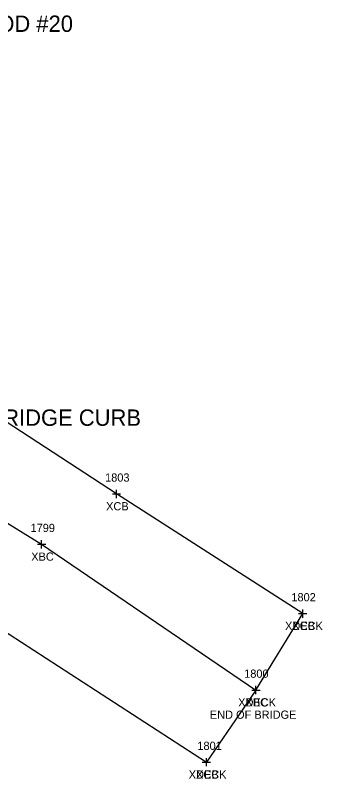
# Model space of a CAD drawing. Extents: x 1657482 to 1661439, y 647981 to 649041.
# Drawn here: x 1660007.4 to 1660044.9, y 647996.3 to 648089.3 of the extents above; entities that cross this region are included whole.
import ezdxf

# ---------------------------------------------------------------- set-up
doc = ezdxf.new("R2010")
doc.units = 0
for name, color, linetype in [('B_A', 7, 'Continuous'), ('B_C', 7, 'Continuous'), ('B_I', 7, 'Continuous'), ('B_TIC', 7, 'Continuous'), ('BDC', 7, 'Continuous'), ('BELB', 7, 'Continuous'), ('C_C', 7, 'Continuous'), ('L_C', 7, 'Continuous')]:
    doc.layers.add(name, color=color, linetype=linetype)

msp = doc.modelspace()

# ---------------------------------------------------------------- linework, layer by layer
at = {"layer": 'B_TIC'}
for p, q in [((1660019.762, 648030.97), (1660019.837, 648030.97)), ((1660010.639, 648024.833), (1660010.715, 648024.833)), ((1660042.454, 648016.386), (1660042.529, 648016.386)), ((1660042.454, 648016.386), (1660042.529, 648016.386)), ((1660036.747, 648007.069), (1660036.823, 648007.069)), ((1660036.747, 648007.069), (1660036.823, 648007.069)), ((1660036.747, 648007.069), (1660036.823, 648007.069)), ((1660030.717, 647998.276), (1660030.792, 647998.276)), ((1660030.717, 647998.276), (1660030.792, 647998.276))]:
    msp.add_line(p, q, dxfattribs=at)
for points in [[(1660019.758, 648030.47), (1660019.758, 648031.47)], [(1660019.258, 648030.97), (1660020.258, 648030.97)], [(1660010.136, 648024.833), (1660011.136, 648024.833)], [(1660010.636, 648024.333), (1660010.636, 648025.333)], [(1660041.95, 648016.386), (1660042.95, 648016.386)], [(1660041.95, 648016.386), (1660042.95, 648016.386)], [(1660042.45, 648015.886), (1660042.45, 648016.886)], [(1660042.45, 648015.886), (1660042.45, 648016.886)], [(1660036.244, 648007.069), (1660037.244, 648007.069)], [(1660036.244, 648007.069), (1660037.244, 648007.069)], [(1660036.244, 648007.069), (1660037.244, 648007.069)], [(1660036.744, 648006.569), (1660036.744, 648007.569)], [(1660036.744, 648006.569), (1660036.744, 648007.569)], [(1660036.744, 648006.569), (1660036.744, 648007.569)], [(1660030.713, 647997.776), (1660030.713, 647998.776)], [(1660030.713, 647997.776), (1660030.713, 647998.776)], [(1660030.213, 647998.276), (1660031.213, 647998.276)], [(1660030.213, 647998.276), (1660031.213, 647998.276)]]:
    msp.add_lwpolyline(points, dxfattribs=at)
at = {"layer": 'BDC'}
for points in [[(1660042.45, 648016.386), (1660019.758, 648030.97), (1659990.854, 648049.845)], [(1659978.866, 648031.627), (1660003.632, 648015.816), (1660030.713, 647998.276)]]:
    msp.add_lwpolyline(points, dxfattribs=at)
at = {"layer": 'BELB'}
for points in [[(1659984.71, 648040.852), (1660010.636, 648024.833), (1660036.744, 648007.069)], [(1660036.744, 648007.069), (1660042.45, 648016.386)], [(1660036.744, 648007.069), (1660030.713, 647998.276)]]:
    msp.add_lwpolyline(points, dxfattribs=at)

# ---------------------------------------------------------------- texts
at = {"layer": 'B_A'}
for s, p in [('XCB', (1660018.494, 648028.97)), ('XBC', (1660009.372, 648022.833)), ('XDECK', (1660040.293, 648014.386)), ('XCB', (1660041.187, 648014.386)), ('XDECK', (1660034.586, 648005.069)), ('XDECK', (1660034.586, 648005.069)), ('XBC', (1660035.48, 648005.069)), ('XDECK', (1660028.556, 647996.276)), ('XCB', (1660029.45, 647996.276))]:
    msp.add_text(s, height=1, dxfattribs=at).set_placement(p)
at = {"layer": 'B_C'}
msp.add_text('END OF BRIDGE', height=1, dxfattribs=at).set_placement((1660031.13, 648003.569))
at = {"layer": 'B_I'}
for s, p in [('1803', (1660018.372, 648032.47)), ('1799', (1660009.285, 648026.333)), ('1802', (1660041.065, 648017.886)), ('1802', (1660041.065, 648017.886)), ('1800', (1660035.315, 648008.569)), ('1800', (1660035.315, 648008.569)), ('1800', (1660035.315, 648008.569)), ('1801', (1660029.611, 647999.776)), ('1801', (1660029.611, 647999.776))]:
    msp.add_text(s, height=1, dxfattribs=at).set_placement(p)
at = {"layer": 'C_C'}
msp.add_text('NAIL IN CONCRETE BRIDGE CURB', height=2, dxfattribs=at).set_placement((1659978.317, 648039.273))
at = {"layer": 'L_C'}
msp.add_text('2 STORY WOOD #20', height=2, dxfattribs=at).set_placement((1659988.451, 648087.281))

doc.saveas('drawing.dxf')
